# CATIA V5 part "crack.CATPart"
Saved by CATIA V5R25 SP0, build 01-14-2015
Part number: crack
Bounding box of the stored display mesh (mm): x -40 to 40, y -11 to 11, z -21 to 10
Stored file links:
  C:\Users\feridun\Desktop\krank biyel\crack.CATPart
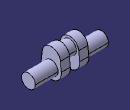
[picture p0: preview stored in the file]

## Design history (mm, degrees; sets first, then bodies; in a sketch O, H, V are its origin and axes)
Body1 (main body)
  Sketch1 on yz-plane, origin (0, 0, 0), H (0, 1, 0), V (0, 0, 1)
    circle A1 centre (0, 0) radius 7.5
    radius A1 = 7.5
  Pad1: profile Sketch1, direction (1, 0, 0), length 5
  Sketch2 on end face of Pad1, origin (5, 0, 0), H (0, 1, 0), V (0, 0, 1)
    arc A1 centre (0, 0) radius 10 from (9.9499, 1) to (-9.9499, 1) ccw
    arc A2 centre (0, -10) radius 11 from (-10.9449, -8.9) to (10.9449, -8.9) ccw
    point P1 (0, -10)
    line L1 (10.9449, -8.9) -> (9.9499, 1)
    line L2 (-10.9449, -8.9) -> (-9.9499, 1)
    radius A1 = 10
    radius A2 = 11
    distance H P1 = 10
    coincidence: P1 V
    tangency: L1 A2, L1 A1, L2 A2, L2 A1
  Pad2: profile Sketch2, direction (1, 0, 0), length 10
  Sketch3 on end face of Pad2, origin (15, 0, 0), H (0, 1, 0), V (0, 0, 1)
    circle A1 centre (0, -10) radius 7.5
    reference projected arc E1 centre (0, -10) radius 11 from (-10.9449, -8.9) to (10.9449, -8.9) ccw from edge [face of Pad2 from Sketch2.A2 | end face of Pad2]
    radius A1 = 7.5
    concentricity: E1 A1
  Pad3: profile Sketch3, direction (1, 0, 0), length 25
  Mirror1: of the body so far, about start face of Pad1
